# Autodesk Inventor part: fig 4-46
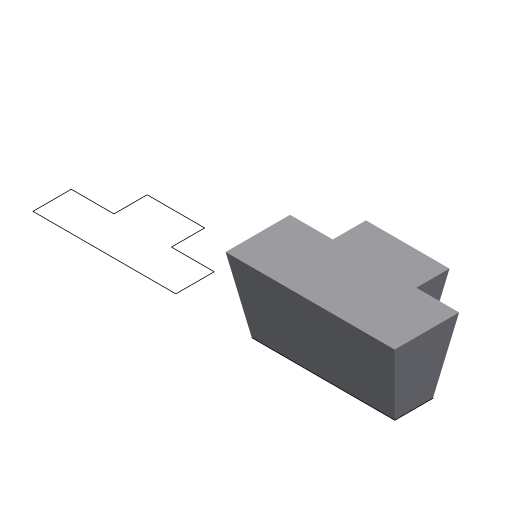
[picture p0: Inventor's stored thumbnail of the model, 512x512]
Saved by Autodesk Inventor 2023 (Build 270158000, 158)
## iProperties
Created: 2004-05
Part Number: fig 4-46
Document SubType Name: Modeling
Designer: CADCIM Technologies
Manufacturer: Standard
Standards Organization: Custom
Density: 1 g/cm^3
Material: Generic
Appearance: Default
Author: CADCIM Technologies
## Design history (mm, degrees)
sketch "Sketch1"
  geometry: L1 (31.783, 34.561)-(31.783, 22.933); L2 (31.783, 22.933)-(16.796, 22.933); L3 (16.796, 22.933)-(16.796, 9.496); L4 (16.796, 9.496)-(66.925, 9.496); L5 (66.925, 9.496)-(66.925, 22.933); L6 (66.925, 22.933)-(51.938, 22.933); L7 (51.938, 22.933)-(51.938, 34.561); L8 (51.938, 34.561)-(31.783, 34.561); L9 (-45.013, 34.561)-(-45.013, 22.933); L10 (-45.013, 22.933)-(-60, 22.933); L11 (-60, 22.933)-(-60, 9.496); L12 (-60, 9.496)-(-9.871, 9.496); L13 (-9.871, 9.496)-(-9.871, 22.933); L14 (-9.871, 22.933)-(-24.858, 22.933); L15 (-24.858, 22.933)-(-24.858, 34.561); L16 (-24.858, 34.561)-(-45.013, 34.561)
  constraints: 32 end point, 10 parallel, 4 equal length, 2 collinear, 2 perpendicular, 2 vertical
extrude "Extrusion2" new body sketch "Sketch1" distance "d2" = 26; taper "d3" = 10 deg
body "Solid2"
